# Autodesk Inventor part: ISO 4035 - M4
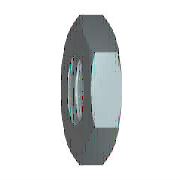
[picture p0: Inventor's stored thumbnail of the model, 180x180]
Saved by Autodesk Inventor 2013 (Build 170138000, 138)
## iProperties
Created: 2012-02
Part Number: ISO 4035 - M4
Material: Edelstahl, 440C
Description: Sechskantmuttern, niedrige Form (mit Fase) - Produktklasse A und B
Document SubType Name: Modeling
Standard: ISO 4035
Designer: SteffenHaase
Standard Revision: Third edition 1999-08-15
Standards Organization: ISO
Language: de-DE
Size Designation: M4
Categories: <MemberInstance><Categories><Category DisplayName="Verbindungselemente" InternalName="e4da775c-781d-43d5-af7c-5136215cf5a6" Mnemonic="FSTN"><Category DisplayNam
Density: 7.75 g/cm^3
IsCustomPart: 0
Author: SteffenHaase
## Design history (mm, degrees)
sketch "Skizze1"
  geometry: L1 (-4.041, 0)-(-2.021, 3.5); L2 (-2.021, 3.5)-(2.021, 3.5); L3 (2.021, 3.5)-(4.041, 0); L4 (4.041, 0)-(2.021, -3.5); L5 (2.021, -3.5)-(-2.021, -3.5); L6 (-2.021, -3.5)-(-4.041, 0); 2 further points
  constraints: 12 end point, 1 coincident, 1 horizontal, 11 other
  dimensions: "d0" = 8.0829 distance of L3.end L1.start (= 1.1547 x SW)
extrude "Körper" new body sketch "Skizze1" distance "d1" = 2.2 (= KOH); taper "d2" = 0 deg
sketch "Skizze2"
  geometry: L1 (0, 2.021)-(0, 4.041) reference; L2 (0, 4.041)-(2.2, 4.041) reference; L3 (2.2, 2.021)-(2.2, 4.041) reference; L4 (-0.44, 0)-(2.64, 0) reference; L5 (0.63, 4.041)-(0, 2.95); L6 (1.57, 4.041)-(2.2, 2.95)
  constraints: 4 end point, 4 point on line
  dimensions: "d3" = 30 deg angle of L1 L5 (= ANG1); "d4" = 30 deg angle of L3 L6 (= ANG2); "d5" = 5.9 diameter of L5.end L4 (= SW0); "d6" = 5.9 diameter of L6.end L4 (= SW01)
revolve "Fase1" sketch "Skizze2" stored, may be unused: angle "d7" = 90 deg
sketch "Skizze3"
  geometry: 4 further points
  constraints: 1 coincident, 1 other
hole "Gewinde" sketch "Skizze3" at (0, 0) diameter "d25" = 3.242; stored, may be unused: countersink angle "d29" = 82 deg, drill point angle "d31" = 118 deg; dims "d26" = 6, "d27" = 4, "d28" = 2, "d30" = 8
workaxis "Work Axis1"
workplane "Work Plane1"
body "Solid1"
chamfer "Fase2" distance "d8" = 0.37889 (= -0.5 x GD1 + 0.5 x NND); stored, may be unused: angle "d9" = 30 deg, second distance "d40" = 0.37889 (= -0.5 x GD1 + 0.5 x NND)
chamfer "Fase3" distance "d10" = 0.37889 (= -0.5 x GD1 + 0.5 x NND); stored, may be unused: angle "d11" = 30 deg, second distance "d41" = 0.37889 (= -0.5 x GD1 + 0.5 x NND)
other parameters: "ANG1" = 30 deg [user parameter; used in 1 equation term], "ANG2" = 30 deg [user parameter; used in 1 equation term], "NND" = 4 [user parameter; used in 4 equation terms], "KOH" = 2.2 [user parameter; used in 1 equation term], "SW" = 7 [user parameter; used in 2 equation terms], "SW0" = 5.9 [user parameter; used in 2 equation terms], "SW01" = 5.9 (= SW0) [user parameter; used in 1 equation term], "GD1" = 3.24223 (computed from THREADDIA, PTC, TOA) [user parameter; used in 4 equation terms], "d13" = 0, "d14" = 0, "d39" = 0, "d42" = 0, "GUL" = 0.37889 (= 0.541266 x PTC) [user parameter], "TPU" = 14.28571 (computed from PTC) [user parameter], "THREADDIA" = 4 [user parameter; used in 1 equation term], "TOA" = 30 deg [user parameter; used in 1 equation term], "PTC" = 0.7 [user parameter; used in 4 equation terms], "E0" = 8.085 (= 1.155 x SW) [user parameter], "GAL" = 0.37889 (= 0.541266 x PTC) [user parameter]
